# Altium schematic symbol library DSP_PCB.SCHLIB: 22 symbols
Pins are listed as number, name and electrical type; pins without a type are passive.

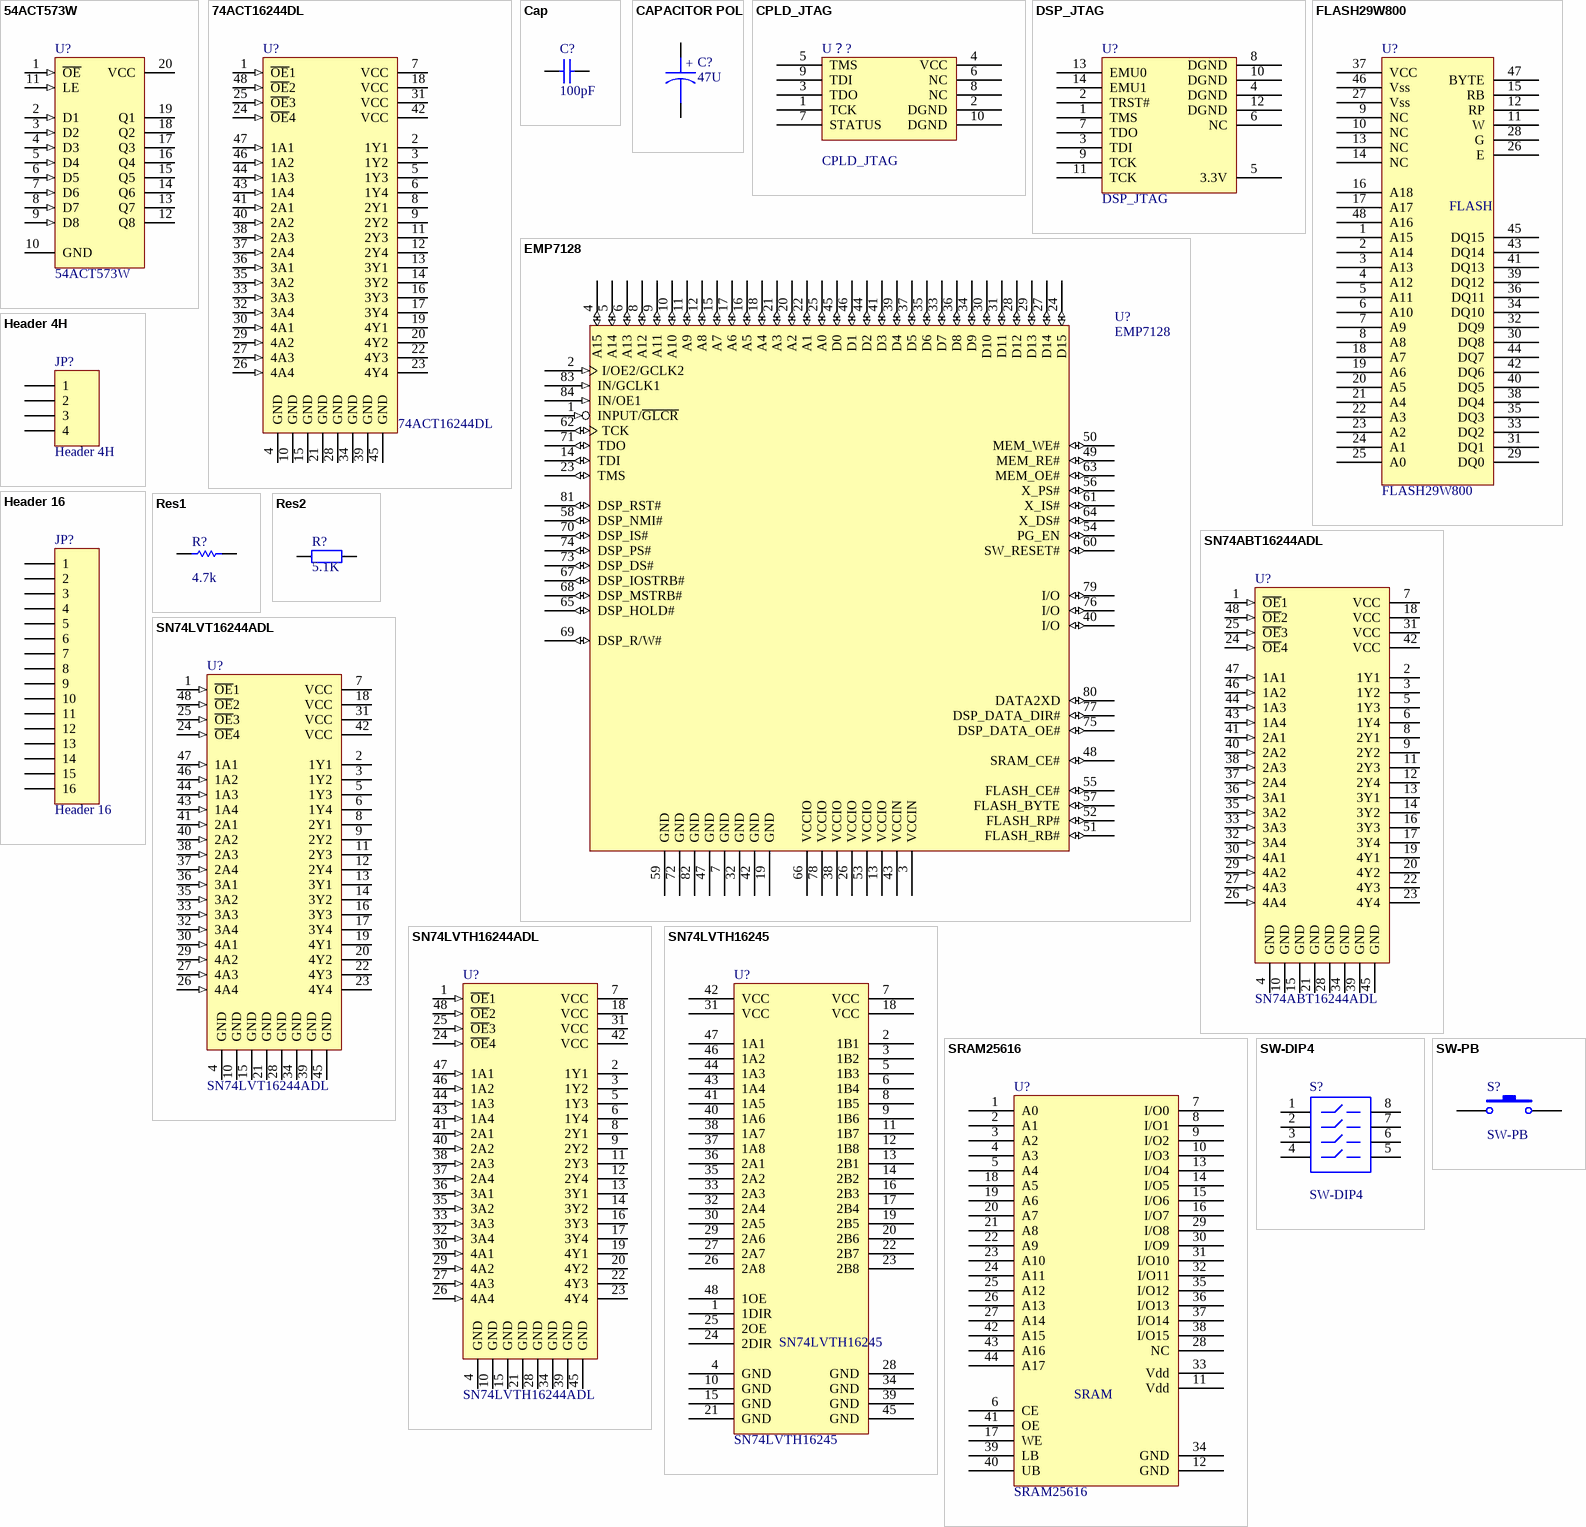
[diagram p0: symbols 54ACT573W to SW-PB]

## 54ACT573W
designator U?
Octal D-Type Transparent Latch with 3-State Outputs; Manufacturer: Texas Instruments; Package Information: Latest Revision: Jan-1995; Class I: Logic
footprint CDFP-G20/C10
signal-integrity model 54ACT573W
pins: 1 ~{OE} (in), 2 D1 (in), 3 D2 (in), 4 D3 (in), 5 D4 (in), 6 D5 (in), 7 D6 (in), 8 D7 (in), 9 D8 (in), 10 GND (power), 11 LE (in), 12 Q8 (hiz), 13 Q7 (hiz), 14 Q6 (hiz), 15 Q5 (hiz), 16 Q4 (hiz), 17 Q3 (hiz), 18 Q2 (hiz), 19 Q1 (hiz), 20 VCC (power)

## 74ACT16244DL
designator U?
16-Bit Buffer/Line Driver with 3-State Outputs; Manufacturer: Texas Instruments; Package Information: Latest Revision: Jan-1998; Class I: Logic
footprint SSO-G48
signal-integrity model 74ACT16244DL
pins: 1 ~{OE}1 (in), 2 1Y1 (hiz), 3 1Y2 (hiz), 4 GND (power), 5 1Y3 (hiz), 6 1Y4 (hiz), 7 VCC (power), 8 2Y1 (hiz), 9 2Y2 (hiz), 10 GND (power), 11 2Y3 (hiz), 12 2Y4 (hiz), 13 3Y1 (hiz), 14 3Y2 (hiz), 15 GND (power), 16 3Y3 (hiz), 17 3Y4 (hiz), 18 VCC (power), 19 4Y1 (hiz), 20 4Y2 (hiz), 21 GND (power), 22 4Y3 (hiz), 23 4Y4 (hiz), 24 ~{OE}4 (in), 25 ~{OE}3 (in), 26 4A4 (in), 27 4A3 (in), 28 GND (power), 29 4A2 (in), 30 4A1 (in), 31 VCC (power), 32 3A4 (in), 33 3A3 (in), 34 GND (power), 35 3A2 (in), 36 3A1 (in), 37 2A4 (in), 38 2A3 (in), 39 GND (power), 40 2A2 (in), 41 2A1 (in), 42 VCC (power), 43 1A4 (in), 44 1A3 (in), 45 GND (power), 46 1A2 (in), 47 1A1 (in), 48 ~{OE}2 (in)

## Cap
designator C?, comment 100pF
Capacitor; Manufacturer: Generic Components; Class I: Passive
simulation model CAP (Capacitor)
signal-integrity model Cap
footprint CC2012-0805
pins: 1, 2

## CAPACITOR POL
designator C?, comment 47U
Capacitor
footprint RB5-10.5
pins: 1, 2

## CPLD_JTAG
designator U？?
footprint IDC10
pins: 1 TCK, 2 DGND, 3 TDO, 4 VCC, 5 TMS, 6 NC, 7 STATUS, 8 NC, 9 TDI, 10 DGND

## DSP_JTAG
designator U?
DSP_JTAG
footprint IDC14
pins: 1 TMS, 2 TRST#, 3 TDI, 4 DGND, 5 3.3V, 6 NC, 7 TDO, 8 DGND, 9 TCK, 10 DGND, 11 TCK, 12 DGND, 13 EMU0, 14 EMU1

## EMP7128
designator U?
CPLD
footprint HPLCC84
pins: 1 INPUT/~{GLCR} (in), 2 I/OE2/GCLK2 (in), 3 VCCIN (power), 4 A15 (io), 5 A14 (io), 6 A13 (io), 7 GND (power), 8 A12 (io), 9 A11 (io), 10 A10 (io), 11 A9 (io), 12 A8 (io), 13 VCCIO (power), 14 TDI (io), 15 A7 (io), 16 A5 (io), 17 A6 (io), 18 A4 (io), 19 GND (power), 20 A2 (io), 21 A3 (io), 22 A1 (io), 23 TMS (io), 24 D15 (io), 25 A0 (io), 26 VCCIO (power), 27 D14 (io), 28 D12 (io), 29 D13 (io), 30 D10 (io), 31 D11 (io), 32 GND (power), 33 D7 (io), 34 D9 (io), 35 D6 (io), 36 D8 (io), 37 D5 (io), 38 VCCIO (power), 39 D4 (io), 40 I/O (io), 41 D3 (io), 42 GND (power), 43 VCCIN (power), 44 D2 (io), 45 D0 (io), 46 D1 (io), 47 GND (power), 48 SRAM_CE# (io), 49 MEM_RE# (io), 50 MEM_WE# (io), 51 FLASH_RB# (io), 52 FLASH_RP# (io), 53 VCCIO (power), 54 PG_EN (io), 55 FLASH_CE# (io), 56 X_PS# (io), 57 FLASH_BYTE (io), 58 DSP_NMI# (io), 59 GND (power), 60 SW_RESET# (io), 61 X_IS# (io), 62 TCK (io), 63 MEM_OE# (io), 64 X_DS# (io), 65 DSP_HOLD# (io), 66 VCCIO (power), 67 DSP_IOSTRB# (io), 68 DSP_MSTRB# (io), 69 DSP_R/W# (io), 70 DSP_IS# (io), 71 TDO (io), 72 GND (power), 73 DSP_DS# (io), 74 DSP_PS# (io), 75 DSP_DATA_OE# (io), 76 I/O (io), 77 DSP_DATA_DIR# (io), 78 VCCIO (power), 79 I/O (io), 80 DATA2XD (io), 81 DSP_RST# (io), 82 GND (power), 83 IN/GCLK1 (in), 84 IN/OE1 (in)

## FLASH29W800
designator U?
FLASH RAM
footprint TSSO12X20-G48/P.5
pins: 1 A15, 2 A14, 3 A13, 4 A12, 5 A11, 6 A10, 7 A9, 8 A8, 9 NC, 10 NC, 11 W, 12 RP, 13 NC, 14 NC, 15 RB, 16 A18, 17 A17, 18 A7, 19 A6, 20 A5, 21 A4, 22 A3, 23 A2, 24 A1, 25 A0, 26 E, 27 Vss, 28 G, 29 DQ0, 30 DQ8, 31 DQ1, 32 DQ9, 33 DQ2, 34 DQ10, 35 DQ3, 36 DQ11, 37 VCC, 38 DQ4, 39 DQ12, 40 DQ5, 41 DQ13, 42 DQ6, 43 DQ14, 44 DQ7, 45 DQ15, 46 Vss, 47 BYTE, 48 A16

## Header 4H
designator JP?
Header, 4-Pin,  Right Angle; Manufacturer: Generic Components; Class I: Connector
footprint HDR1X4H
signal-integrity model Connector
pins: 1, 2, 3, 4

## Header 16
designator JP?
Header, 16-Pin; Manufacturer: Generic Components; Class I: Connector
footprint HDR1X16
signal-integrity model Connector
pins: 1, 2, 3, 4, 5, 6, 7, 8, 9, 10, 11, 12, 13, 14, 15, 16

## Res1
designator R?, comment 4.7k
Resistor; Manufacturer: Generic Components; Class I: Passive; Value: 1K
footprint AXIAL-0.3
simulation model RESISTOR (Resistor)
signal-integrity model Res1
pins: 1, 2

## Res2
designator R?, comment 5.1K
Resistor; Manufacturer: Generic Components; Class I: Passive
simulation model RESISTOR (Resistor)
signal-integrity model Res2
footprint R2012-0805
pins: 1, 2

## SN74ABT16244ADL
designator U?
16-Bit Buffer/Driver with 3-State Outputs; Manufacturer: Texas Instruments; Package Information: Latest Revision: Jan-1998; Class I: Logic; Class II: Buffer/Line Driver
footprint SSO-G48
signal-integrity model SN74ABT16244ADL
pins: 1 ~{OE}1 (in), 2 1Y1 (hiz), 3 1Y2 (hiz), 4 GND (power), 5 1Y3 (hiz), 6 1Y4 (hiz), 7 VCC (power), 8 2Y1 (hiz), 9 2Y2 (hiz), 10 GND (power), 11 2Y3 (hiz), 12 2Y4 (hiz), 13 3Y1 (hiz), 14 3Y2 (hiz), 15 GND (power), 16 3Y3 (hiz), 17 3Y4 (hiz), 18 VCC (power), 19 4Y1 (hiz), 20 4Y2 (hiz), 21 GND (power), 22 4Y3 (hiz), 23 4Y4 (hiz), 24 ~{OE}4 (in), 25 ~{OE}3 (in), 26 4A4 (in), 27 4A3 (in), 28 GND (power), 29 4A2 (in), 30 4A1 (in), 31 VCC (power), 32 3A4 (in), 33 3A3 (in), 34 GND (power), 35 3A2 (in), 36 3A1 (in), 37 2A4 (in), 38 2A3 (in), 39 GND (power), 40 2A2 (in), 41 2A1 (in), 42 VCC (power), 43 1A4 (in), 44 1A3 (in), 45 GND (power), 46 1A2 (in), 47 1A1 (in), 48 ~{OE}2 (in)

## SN74LVT16244ADL
designator U?
3.3-V ABT 16-Bit Buffer/Driver with 3-State Outputs; Manufacturer: Texas Instruments; Package Information: Latest Revision: Jan-1998; Class I: Logic; Class II: Buffer/Line Driver
footprint SSO-G48
signal-integrity model SN74LVT16244ADL
pins: 1 ~{OE}1 (in), 2 1Y1 (hiz), 3 1Y2 (hiz), 4 GND (power), 5 1Y3 (hiz), 6 1Y4 (hiz), 7 VCC (power), 8 2Y1 (hiz), 9 2Y2 (hiz), 10 GND (power), 11 2Y3 (hiz), 12 2Y4 (hiz), 13 3Y1 (hiz), 14 3Y2 (hiz), 15 GND (power), 16 3Y3 (hiz), 17 3Y4 (hiz), 18 VCC (power), 19 4Y1 (hiz), 20 4Y2 (hiz), 21 GND (power), 22 4Y3 (hiz), 23 4Y4 (hiz), 24 ~{OE}4 (in), 25 ~{OE}3 (in), 26 4A4 (in), 27 4A3 (in), 28 GND (power), 29 4A2 (in), 30 4A1 (in), 31 VCC (power), 32 3A4 (in), 33 3A3 (in), 34 GND (power), 35 3A2 (in), 36 3A1 (in), 37 2A4 (in), 38 2A3 (in), 39 GND (power), 40 2A2 (in), 41 2A1 (in), 42 VCC (power), 43 1A4 (in), 44 1A3 (in), 45 GND (power), 46 1A2 (in), 47 1A1 (in), 48 ~{OE}2 (in)

## SN74LVTH16244ADL
designator U?
3.3-V ABT 16-Bit Buffer/Driver with 3-State Outputs; Manufacturer: Texas Instruments; Package Information: Latest Revision: Jan-1998; Class I: Logic; Class II: Buffer/Line Driver
footprint SSO-G48
pins: 1 ~{OE}1 (in), 2 1Y1 (hiz), 3 1Y2 (hiz), 4 GND (power), 5 1Y3 (hiz), 6 1Y4 (hiz), 7 VCC (power), 8 2Y1 (hiz), 9 2Y2 (hiz), 10 GND (power), 11 2Y3 (hiz), 12 2Y4 (hiz), 13 3Y1 (hiz), 14 3Y2 (hiz), 15 GND (power), 16 3Y3 (hiz), 17 3Y4 (hiz), 18 VCC (power), 19 4Y1 (hiz), 20 4Y2 (hiz), 21 GND (power), 22 4Y3 (hiz), 23 4Y4 (hiz), 24 ~{OE}4 (in), 25 ~{OE}3 (in), 26 4A4 (in), 27 4A3 (in), 28 GND (power), 29 4A2 (in), 30 4A1 (in), 31 VCC (power), 32 3A4 (in), 33 3A3 (in), 34 GND (power), 35 3A2 (in), 36 3A1 (in), 37 2A4 (in), 38 2A3 (in), 39 GND (power), 40 2A2 (in), 41 2A1 (in), 42 VCC (power), 43 1A4 (in), 44 1A3 (in), 45 GND (power), 46 1A2 (in), 47 1A1 (in), 48 ~{OE}2 (in)

## SN74LVTH16245
designator U?
footprint TSOP48
pins: 1 1DIR, 2 1B1, 3 1B2, 4 GND, 5 1B3, 6 1B4, 7 VCC, 8 1B5, 9 1B6, 10 GND, 11 1B7, 12 1B8, 13 2B1, 14 2B2, 15 GND, 16 2B3, 17 2B4, 18 VCC, 19 2B5, 20 2B6, 21 GND, 22 2B7, 23 2B8, 24 2DIR, 25 2OE, 26 2A8, 27 2A7, 28 GND, 29 2A6, 30 2A5, 31 VCC, 32 2A4, 33 2A3, 34 GND, 35 2A2, 36 2A1, 37 1A8, 38 1A7, 39 GND, 40 1A6, 41 1A5, 42 VCC, 43 1A4, 44 1A3, 45 GND, 46 1A2, 47 1A1, 48 1OE

## SRAM25616
designator U?
SRAM
footprint TSOP44
pins: 1 A0, 2 A1, 3 A2, 4 A3, 5 A4, 6 CE, 7 I/O0, 8 I/O1, 9 I/O2, 10 I/O3, 11 Vdd, 12 GND, 13 I/O4, 14 I/O5, 15 I/O6, 16 I/O7, 17 WE, 18 A5, 19 A6, 20 A7, 21 A8, 22 A9, 23 A10, 24 A11, 25 A12, 26 A13, 27 A14, 28 NC, 29 I/O8, 30 I/O9, 31 I/O10, 32 I/O11, 33 Vdd, 34 GND, 35 I/O12, 36 I/O13, 37 I/O14, 38 I/O15, 39 LB, 40 UB, 41 OE, 42 A15, 43 A16, 44 A17

## SW-DIP4
designator S?
DIP Switch; Manufacturer: Generic Components
footprint DIP-8
simulation model dpsw4 (Spice Subcircuit)
pins: 1, 2, 3, 4, 5, 6, 7, 8

## SW-PB
designator S?
Switch; Manufacturer: Generic Components
footprint SPST-2
pins: 1, 2

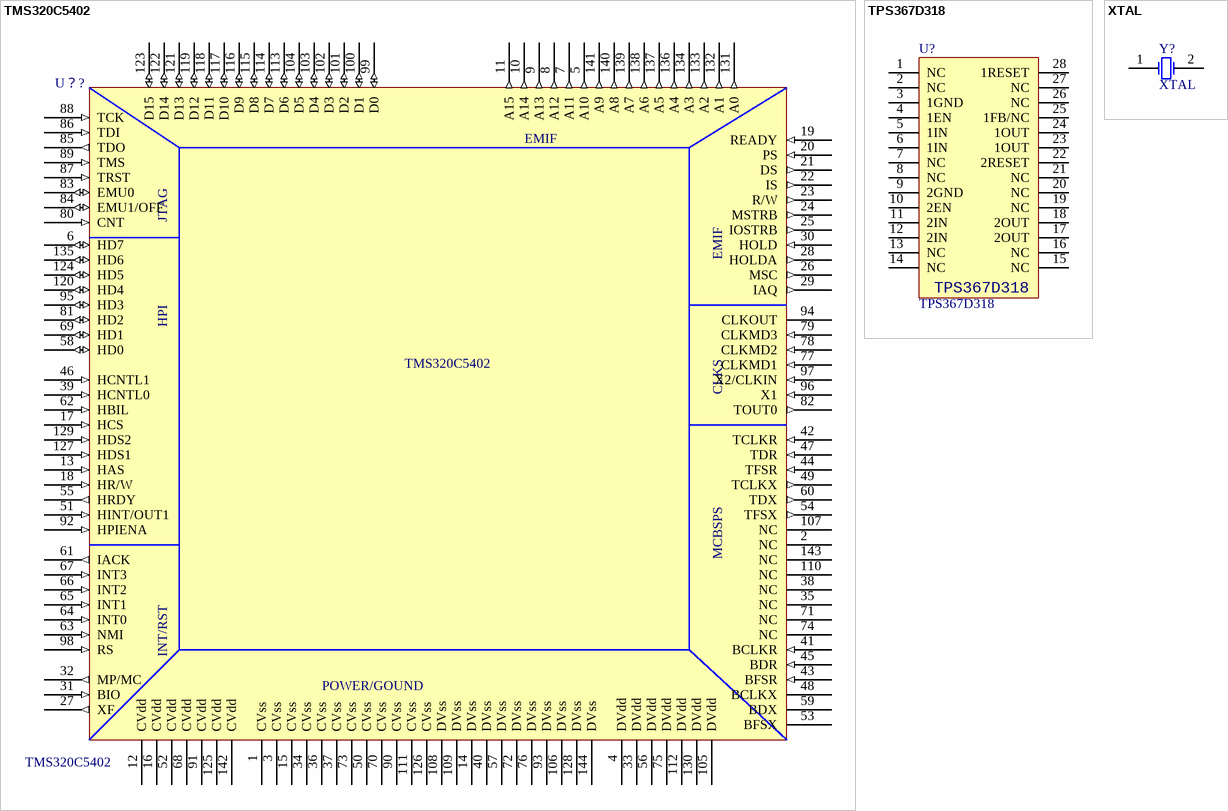
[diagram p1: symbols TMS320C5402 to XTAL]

## TMS320C5402
designator U？?
FIXED-POINT DIGITAL SIGNAL PROCESSORS
footprint QFP144
pins: 1 CVss (power), 2 NC, 3 CVss (power), 4 DVdd (power), 5 A10 (out), 6 HD7 (io), 7 A11 (out), 8 A12 (out), 9 A13 (out), 10 A14 (out), 11 A15 (out), 12 CVdd (power), 13 HAS (in), 14 DVss (power), 15 CVss (power), 16 CVdd (power), 17 HCS (in), 18 HR/W (in), 19 READY (in), 20 PS (in), 21 DS (out), 22 IS (out), 23 R/W (out), 24 MSTRB (out), 25 IOSTRB (out), 26 MSC (out), 27 XF (out), 28 HOLDA (out), 29 IAQ (out), 30 HOLD (in), 31 BIO (in), 32 MP/MC (out), 33 DVdd (power), 34 CVss (power), 35 NC, 36 CVss (power), 37 CVss (power), 38 NC, 39 HCNTL0 (in), 40 DVss (power), 41 BCLKR (in), 42 TCLKR (in), 43 BFSR (in), 44 TFSR (in), 45 BDR (in), 46 HCNTL1 (in), 47 TDR (in), 48 BCLKX, 49 TCLKX (out), 50 CVss (power), 51 HINT/OUT1 (in), 52 CVdd (power), 53 BFSX, 54 TFSX (out), 55 HRDY (out), 56 DVdd (power), 57 DVss (power), 58 HD0 (io), 59 BDX, 60 TDX (out), 61 IACK (out), 62 HBIL (in), 63 NMI (in), 64 INT0 (in), 65 INT1 (in), 66 INT2 (in), 67 INT3 (in), 68 CVdd (power), 69 HD1 (io), 70 CVss (power), 71 NC, 72 DVss (power), 73 CVss (power), 74 NC, 75 DVdd (power), 76 DVss (power), 77 CLKMD1 (in), 78 CLKMD2 (in), 79 CLKMD3 (in), 80 CNT (in), 81 HD2 (io), 82 TOUT0 (out), 83 EMU0 (io), 84 EMU1/OFF (io), 85 TDO (out), 86 TDI (in), 87 TRST (in), 88 TCK (in), 89 TMS (in), 90 CVss (power), 91 CVdd (power), 92 HPIENA (in), 93 DVss (power), 94 CLKOUT, 95 HD3 (io), 96 X1 (in), 97 X2/CLKIN (in), 98 RS (in), 99 D0 (io), 100 D1 (io), 101 D2 (io), 102 D3 (io), 103 D4 (io), 104 D5 (io), 105 DVdd (power), 106 DVss (power), 107 NC, 108 DVss (power), 109 DVss (power), 110 NC, 111 CVss (power), 112 DVdd (power), 113 D6 (io), 114 D7 (io), 115 D8 (io), 116 D9 (io), 117 D10 (io), 118 D11 (io), 119 D12 (io), 120 HD4 (io), 121 D13 (io), 122 D14 (io), 123 D15 (io), 124 HD5 (io), 125 CVdd (power), 126 CVss (power), 127 HDS1 (in), 128 DVss (power), 129 HDS2 (in), 130 DVdd (power), 131 A0 (out), 132 A1 (out), 133 A2 (out), 134 A3 (out), 135 HD6 (io), 136 A4 (out), 137 A5 (out), 138 A6 (out), 139 A7 (out), 140 A8 (out), 141 A9 (out), 142 CVdd (power), 143 NC, 144 DVss (power)

## TPS367D318
designator U?
POWRE; Manufacturer: Texas Instruments
footprint TSSO10X6-G28
pins: 1 NC, 2 NC, 3 1GND (power), 4 1EN, 5 1IN, 6 1IN, 7 NC, 8 NC, 9 2GND (power), 10 2EN, 11 2IN, 12 2IN, 13 NC, 14 NC, 15 NC, 16 NC, 17 2OUT, 18 2OUT, 19 NC, 20 NC, 21 NC, 22 2RESET, 23 1OUT, 24 1OUT, 25 1FB/NC, 26 NC, 27 NC, 28 1RESET

## XTAL
designator Y?
Crystal Oscillator; Manufacturer: Generic Components
footprint BCY-W2/D3.1
simulation model XTAL (Spice Subcircuit)
pins: 1 OSC1, 2 OSC2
